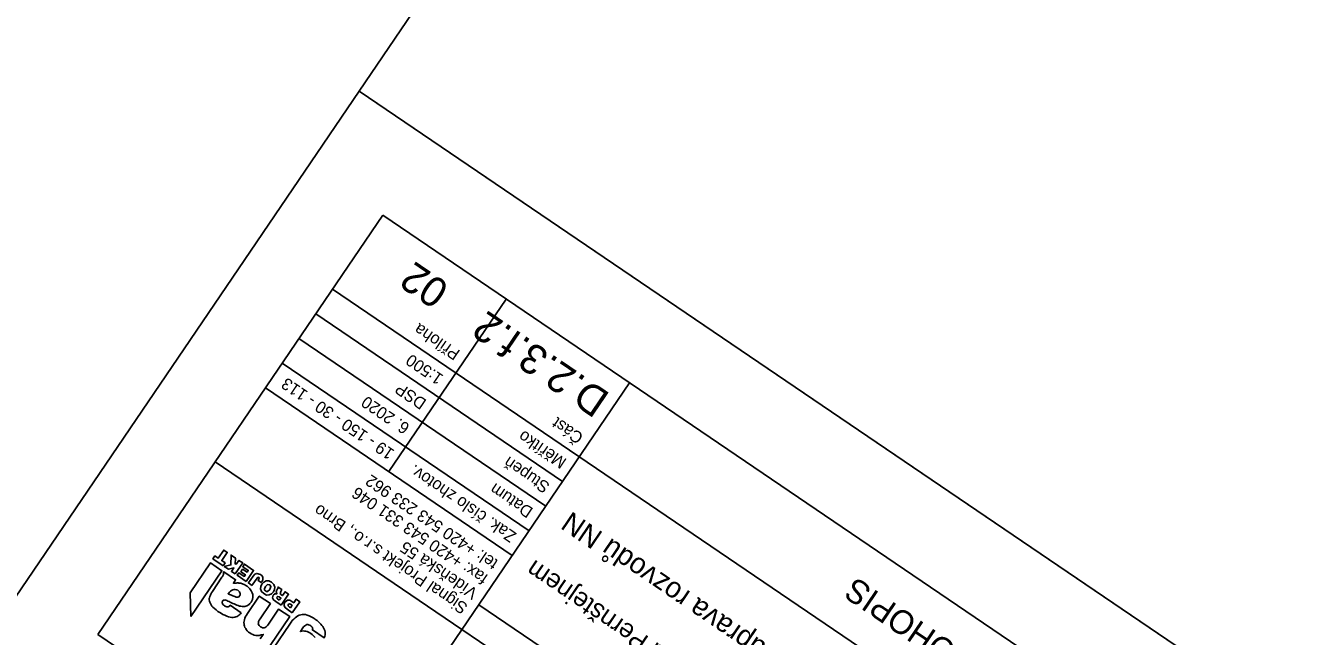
# Model space of a CAD drawing. Extents: x -620624 to -619936, y -1122925 to -1122325.
# Drawn here: x -620568.3 to -620461.4, y -1122493.6 to -1122442.4 of the extents above; entities that cross this region are included whole.
import ezdxf

# ---------------------------------------------------------------- set-up
doc = ezdxf.new("R2010")
doc.units = 0
for name, color, linetype in [('Info o rozpiskách', 7, 'Continuous'), ('popis', 7, 'Continuous'), ('Ramečky', 7, 'Continuous'), ('RÁMY', 7, 'Continuous'), ('Text', 7, 'Continuous'), ('Text barevný', 7, 'Continuous')]:
    doc.layers.add(name, color=color, linetype=linetype)

msp = doc.modelspace()

# ---------------------------------------------------------------- linework, layer by layer
at = {"layer": 'Info o rozpiskách'}
for points in [[(-620551.78, -1122487.67), (-620552.63, -1122487.09), (-620552.47, -1122486.85), (-620552.2, -1122487.04), (-620551.73, -1122486.36), (-620551.43, -1122486.56), (-620551.89, -1122487.24), (-620551.62, -1122487.43), (-620551.78, -1122487.67)], [(-620550.77, -1122488.36), (-620551.08, -1122488.15), (-620550.88, -1122487.85), (-620551.34, -1122487.97), (-620551.69, -1122487.73), (-620551.12, -1122487.61), (-620551.11, -1122486.78), (-620550.75, -1122487.03), (-620550.77, -1122487.54), (-620550.65, -1122487.52), (-620550.45, -1122487.23), (-620550.14, -1122487.44), (-620550.77, -1122488.36)], [(-620549.85, -1122488.98), (-620550.6, -1122488.47), (-620550.46, -1122488.26), (-620550.01, -1122488.57), (-620549.91, -1122488.43), (-620550.29, -1122488.17), (-620550.15, -1122487.96), (-620549.77, -1122488.21), (-620549.67, -1122488.07), (-620550.14, -1122487.75), (-620550, -1122487.54), (-620549.23, -1122488.06), (-620549.85, -1122488.98)], [(-620549.36, -1122489.32), (-620549.66, -1122489.11), (-620549.27, -1122488.54), (-620549.12, -1122488.38), (-620548.95, -1122488.32), (-620548.66, -1122488.41), (-620548.52, -1122488.53), (-620548.45, -1122488.67), (-620548.45, -1122488.84), (-620548.53, -1122489.02), (-620548.58, -1122489.09), (-620548.85, -1122488.9), (-620548.76, -1122488.74), (-620548.79, -1122488.65), (-620548.87, -1122488.64), (-620548.94, -1122488.71), (-620549.36, -1122489.32)], [(-620548.38, -1122490.01), (-620548.56, -1122489.84), (-620548.65, -1122489.62), (-620548.63, -1122489.41), (-620548.54, -1122489.21), (-620548.38, -1122489.04), (-620548.18, -1122488.95), (-620547.96, -1122488.95), (-620547.72, -1122489.05), (-620547.53, -1122489.24), (-620547.45, -1122489.46), (-620547.48, -1122489.67), (-620547.57, -1122489.87), (-620547.73, -1122490.04), (-620547.92, -1122490.12), (-620548.15, -1122490.13), (-620548.38, -1122490.01)], [(-620548.22, -1122489.79), (-620548.14, -1122489.83), (-620548.05, -1122489.82), (-620547.87, -1122489.66), (-620547.78, -1122489.42), (-620547.87, -1122489.27), (-620548.07, -1122489.25), (-620548.23, -1122489.4), (-620548.31, -1122489.62), (-620548.3, -1122489.72), (-620548.22, -1122489.79)], [(-620546.91, -1122490.98), (-620547.36, -1122490.67), (-620547.55, -1122490.52), (-620547.64, -1122490.37), (-620547.58, -1122490.14), (-620547.44, -1122490.02), (-620547.27, -1122490.02), (-620547.34, -1122489.84), (-620547.26, -1122489.67), (-620547.21, -1122489.6), (-620547.17, -1122489.52), (-620547.18, -1122489.48), (-620547.17, -1122489.46), (-620546.86, -1122489.67), (-620546.95, -1122489.84), (-620547, -1122490.03), (-620546.94, -1122490.08), (-620546.85, -1122490.15), (-620546.81, -1122490.18), (-620546.59, -1122489.85), (-620546.29, -1122490.06), (-620546.91, -1122490.98)], [(-620547.07, -1122490.56), (-620546.94, -1122490.38), (-620547.08, -1122490.29), (-620547.2, -1122490.25), (-620547.26, -1122490.29), (-620547.28, -1122490.38), (-620547.22, -1122490.46), (-620547.07, -1122490.56)], [(-620545.98, -1122491.61), (-620546.42, -1122491.31), (-620546.58, -1122491.18), (-620546.66, -1122491.03), (-620546.67, -1122490.88), (-620546.6, -1122490.72), (-620546.37, -1122490.55), (-620546.2, -1122490.57), (-620546.01, -1122490.66), (-620545.86, -1122490.77), (-620545.66, -1122490.48), (-620545.36, -1122490.69), (-620545.98, -1122491.61)], [(-620546.14, -1122491.19), (-620546, -1122490.98), (-620546.13, -1122490.9), (-620546.23, -1122490.87), (-620546.32, -1122490.92), (-620546.34, -1122491.02), (-620546.23, -1122491.14), (-620546.14, -1122491.19)]]:
    msp.add_lwpolyline(points, dxfattribs=at)
at = {"layer": 'popis'}
for points in [[(-620554.49, -1122491.92), (-620551.88, -1122488.09), (-620552.84, -1122487.44), (-620554.53, -1122489.93), (-620554.49, -1122491.92)], [(-620550.27, -1122491.62), (-620551.18, -1122490.99), (-620551.24, -1122491.06), (-620551.29, -1122491.1), (-620551.35, -1122491.12), (-620551.41, -1122491.12), (-620551.48, -1122491.12), (-620551.55, -1122491.1), (-620551.6, -1122491.06), (-620551.66, -1122491.02), (-620551.73, -1122490.97), (-620551.8, -1122490.92), (-620551.83, -1122490.85), (-620551.85, -1122490.81), (-620551.86, -1122490.76), (-620551.87, -1122490.71), (-620551.84, -1122490.67), (-620551.83, -1122490.62), (-620551.79, -1122490.59), (-620551.75, -1122490.55), (-620551.69, -1122490.55), (-620551.63, -1122490.54), (-620551.56, -1122490.55), (-620551.47, -1122490.59), (-620551.38, -1122490.63), (-620551.28, -1122490.67), (-620551.18, -1122490.73), (-620551.07, -1122490.78), (-620550.97, -1122490.83), (-620550.86, -1122490.88), (-620550.74, -1122490.92), (-620550.63, -1122490.98), (-620550.52, -1122491), (-620550.42, -1122491.05), (-620550.3, -1122491.07), (-620550.18, -1122491.09), (-620550.06, -1122491.08), (-620549.96, -1122491.09), (-620549.87, -1122491.07), (-620549.79, -1122491.03), (-620549.73, -1122491.01), (-620549.66, -1122490.96), (-620549.6, -1122490.91), (-620549.54, -1122490.85), (-620549.49, -1122490.79), (-620549.44, -1122490.72), (-620549.33, -1122490.51), (-620549.28, -1122490.3), (-620549.29, -1122490.09), (-620549.34, -1122489.94), (-620549.42, -1122489.77), (-620549.53, -1122489.62), (-620549.64, -1122489.5), (-620549.77, -1122489.39), (-620549.83, -1122489.35), (-620549.89, -1122489.32), (-620549.95, -1122489.28), (-620550.03, -1122489.25), (-620550.09, -1122489.23), (-620550.16, -1122489.19), (-620550.23, -1122489.16), (-620550.3, -1122489.14), (-620550.37, -1122489.13), (-620550.45, -1122489.13), (-620550.52, -1122489.11), (-620550.6, -1122489.11), (-620550.68, -1122489.12), (-620550.75, -1122489.13), (-620550.85, -1122489.14), (-620550.92, -1122489.14), (-620550.74, -1122488.85), (-620551.73, -1122488.18), (-620551.76, -1122488.22), (-620551.74, -1122488.31), (-620551.74, -1122488.36), (-620551.74, -1122488.42), (-620551.77, -1122488.45), (-620551.78, -1122488.5), (-620551.8, -1122488.53), (-620551.83, -1122488.58), (-620551.88, -1122488.64), (-620552.68, -1122489.83), (-620552.75, -1122489.93), (-620552.8, -1122490.05), (-620552.84, -1122490.15), (-620552.89, -1122490.25), (-620552.92, -1122490.35), (-620552.94, -1122490.42), (-620552.95, -1122490.52), (-620552.92, -1122490.64), (-620552.89, -1122490.74), (-620552.85, -1122490.83), (-620552.79, -1122490.94), (-620552.72, -1122491.05), (-620552.63, -1122491.14), (-620552.5, -1122491.25), (-620552.36, -1122491.37), (-620552.21, -1122491.51), (-620552.01, -1122491.63), (-620551.8, -1122491.75), (-620551.64, -1122491.83), (-620551.47, -1122491.9), (-620551.32, -1122491.95), (-620551.19, -1122491.98), (-620551.05, -1122492), (-620550.93, -1122492), (-620550.81, -1122491.99), (-620550.72, -1122491.97), (-620550.61, -1122491.94), (-620550.52, -1122491.88), (-620550.47, -1122491.83), (-620550.39, -1122491.77), (-620550.32, -1122491.7), (-620550.27, -1122491.62)], [(-620551.37, -1122490.04), (-620551.37, -1122490.04), (-620551.35, -1122490.01), (-620551.34, -1122490), (-620551.25, -1122489.9), (-620551.17, -1122489.8), (-620551.08, -1122489.75), (-620550.97, -1122489.68), (-620550.86, -1122489.66), (-620550.76, -1122489.67), (-620550.65, -1122489.69), (-620550.55, -1122489.72), (-620550.48, -1122489.77), (-620550.44, -1122489.82), (-620550.41, -1122489.87), (-620550.38, -1122489.93), (-620550.36, -1122489.99), (-620550.34, -1122490.05), (-620550.34, -1122490.11), (-620550.37, -1122490.18), (-620550.46, -1122490.27), (-620550.56, -1122490.31), (-620550.69, -1122490.3), (-620550.81, -1122490.26), (-620550.96, -1122490.2), (-620551.09, -1122490.14), (-620551.24, -1122490.09), (-620551.37, -1122490.04)], [(-620547.85, -1122494.37), (-620546.2, -1122491.94), (-620547.13, -1122491.31), (-620547.97, -1122492.56), (-620548.06, -1122492.69), (-620548.17, -1122492.8), (-620548.25, -1122492.84), (-620548.33, -1122492.88), (-620548.41, -1122492.88), (-620548.49, -1122492.87), (-620548.57, -1122492.83), (-620548.66, -1122492.79), (-620548.73, -1122492.72), (-620548.77, -1122492.67), (-620548.82, -1122492.6), (-620548.83, -1122492.53), (-620548.82, -1122492.45), (-620548.81, -1122492.36), (-620548.75, -1122492.24), (-620548.68, -1122492.13), (-620547.81, -1122490.85), (-620548.75, -1122490.21), (-620549.74, -1122491.68), (-620549.83, -1122491.81), (-620549.91, -1122491.94), (-620549.96, -1122492.07), (-620550, -1122492.21), (-620550.02, -1122492.32), (-620550.04, -1122492.44), (-620550.01, -1122492.56), (-620550.01, -1122492.66), (-620549.99, -1122492.75), (-620549.96, -1122492.85), (-620549.89, -1122492.93), (-620549.84, -1122493.02), (-620549.77, -1122493.12), (-620549.71, -1122493.18), (-620549.64, -1122493.25), (-620549.55, -1122493.31), (-620549.43, -1122493.39), (-620549.29, -1122493.44), (-620549.18, -1122493.49), (-620549.04, -1122493.51), (-620548.9, -1122493.53), (-620548.75, -1122493.52), (-620548.6, -1122493.47), (-620548.42, -1122493.43), (-620548.68, -1122493.81)], [(-620544.07, -1122493.7), (-620544.14, -1122493.6), (-620544.22, -1122493.51), (-620544.31, -1122493.43), (-620544.42, -1122493.36), (-620544.51, -1122493.29), (-620544.61, -1122493.25), (-620544.73, -1122493.19), (-620544.85, -1122493.17), (-620544.96, -1122493.15), (-620545.08, -1122493.14), (-620545.18, -1122493.16), (-620545.3, -1122493.19), (-620545.15, -1122492.96), (-620545.04, -1122492.8), (-620544.93, -1122492.71), (-620544.84, -1122492.66), (-620544.76, -1122492.61), (-620544.68, -1122492.61), (-620544.61, -1122492.63), (-620544.52, -1122492.66), (-620544.44, -1122492.71), (-620544.41, -1122492.73), (-620544.36, -1122492.78), (-620544.32, -1122492.83), (-620544.29, -1122492.87), (-620544.29, -1122492.91), (-620544.27, -1122492.97), (-620544.29, -1122493.01), (-620544.3, -1122493.06), (-620543.32, -1122493.72), (-620543.26, -1122493.58), (-620543.24, -1122493.47), (-620543.24, -1122493.34), (-620543.24, -1122493.23), (-620543.25, -1122493.1), (-620543.32, -1122492.99), (-620543.37, -1122492.89), (-620543.43, -1122492.76), (-620543.5, -1122492.67), (-620543.59, -1122492.58), (-620543.67, -1122492.49), (-620543.76, -1122492.4), (-620543.84, -1122492.33), (-620543.91, -1122492.27), (-620544, -1122492.2), (-620544.07, -1122492.15), (-620544.24, -1122492.04), (-620544.41, -1122491.95), (-620544.58, -1122491.87), (-620544.73, -1122491.82), (-620544.88, -1122491.77), (-620545.02, -1122491.75), (-620545.15, -1122491.76), (-620545.27, -1122491.79), (-620545.4, -1122491.82), (-620545.52, -1122491.88), (-620545.63, -1122491.95), (-620545.75, -1122492.04), (-620545.85, -1122492.15), (-620545.98, -1122492.26), (-620546.08, -1122492.41), (-620546.19, -1122492.58), (-620547.56, -1122494.59)]]:
    msp.add_lwpolyline(points, dxfattribs=at)
at = {"layer": 'Ramečky'}
for p, q in [((-620538.39, -1122458.28), (-620562.27, -1122493.44)), ((-620463.94, -1122508.85), (-620538.39, -1122458.28)), ((-620468.16, -1122515.05), (-620542.61, -1122464.49)), ((-620523.33, -1122480.6), (-620544.01, -1122466.56)), ((-620524.74, -1122482.67), (-620545.42, -1122468.62)), ((-620526.14, -1122484.74), (-620546.82, -1122470.69)), ((-620517.71, -1122472.33), (-620541.59, -1122507.49)), ((-620527.55, -1122486.81), (-620548.23, -1122472.76)), ((-620476.58, -1122527.46), (-620530.35, -1122490.94)), ((-620562.27, -1122493.44), (-620487.82, -1122544.01)), ((-620477.99, -1122529.53), (-620531.76, -1122493.01))]:
    msp.add_line(p, q, dxfattribs=at)
for points in [[(-620537.89, -1122479.78), (-620528.05, -1122465.31)], [(-620531.76, -1122493.01), (-620552.44, -1122478.97)]]:
    msp.add_lwpolyline(points, dxfattribs=at)
at = {"layer": 'RÁMY'}
for points in [[(-620456.95, -1122325.02), (-620370.09, -1122384.01), (-620453.52, -1122506.86), (-620540.39, -1122447.87)], [(-620540.39, -1122447.87), (-620019.21, -1122801.81), (-620102.64, -1122924.66), (-620623.82, -1122570.71)]]:
    msp.add_lwpolyline(points, close=True, dxfattribs=at)

# ---------------------------------------------------------------- texts
at = {"layer": 'Text'}
for s, p in [('Příloha', (-620531.84, -1122469.68)), ('1:500', (-620533.25, -1122471.75)), ('19 - 150 - 30 - 113', (-620537.35, -1122478.03)), ('6. 2020', (-620536.06, -1122475.89)), ('DSP', (-620534.65, -1122473.82)), ('Část', (-620521.5, -1122476.71)), ('Měřítko', (-620522.91, -1122478.78)), ('Stupeň', (-620524.31, -1122480.84)), ('Zak. číslo zhotov.', (-620527.12, -1122484.98)), ('tel: +420 543 233 962', (-620528.66, -1122487.26)), ('Datum', (-620525.72, -1122482.91)), ('fax: +420 543 331 046', (-620529.5, -1122488.5)), ('Signal Projekt s.r.o., Brno', (-620531.19, -1122490.98)), ('Vídeňská 55', (-620530.35, -1122489.74))]:
    msp.add_text(s, height=1, rotation=145.8181, dxfattribs=at).set_placement(p)
at = {"layer": 'Text barevný'}
for s, height, p in [('02', 2.5, (-620532.69, -1122464.17)), ('D.2.3.f.2', 2.5, (-620519.24, -1122473.3)), ('SO 06-06-03 Bystřice nad Pernštějnem, úprava rozvodů NN', 1.7296, (-620471.78, -1122517.58)), ('Oprava zabezpečovacího zařízení v ŽST Bystřice nad Pernštejnem', 1.5589, (-620474.31, -1122522)), ('POLOHOPIS', 2, (-620485.73, -1122497.41))]:
    msp.add_text(s, height=height, rotation=145.8181, dxfattribs=at).set_placement(p)

doc.saveas('drawing.dxf')
